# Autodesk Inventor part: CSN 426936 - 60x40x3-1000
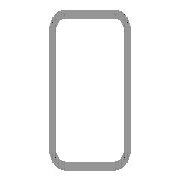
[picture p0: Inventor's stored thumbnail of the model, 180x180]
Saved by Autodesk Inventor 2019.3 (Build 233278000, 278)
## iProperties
Created: 2018-01
Part Number: CSN 426936 - 60x40x3-1000
Material: Ocel, měkká
Description: Tenkostěnné profily ocelové svařované (obdélníkový profil)
Document SubType Name: Modellieren
Standard: CSN 42 6936
Designer: B-hon
Standards Organization: CSN
Language: cs-CZ
Size Designation: 60x40x3-1000
Categories: <MemberInstance><Categories><Category DisplayName="Konstrukční profily" InternalName="089c4875-fa83-4c05-b084-43b9cc11f5ed" Mnemonic="GRDR"><CategoryParameter D
Stock Number: 60x40x3
Density: 7.85 g/cm^3
Appearance: Pololeštěná
IsCustomPart: 1
G_L: 1000,000 mm
Author: B-hon
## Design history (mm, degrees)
node "Počáteční rovina"
node "Koncová rovina"
sketch "Náčrt1"
  geometry: L1 (-14, 30)-(14, 30); L2 (20, 24)-(20, -24); L3 (14, -30)-(-14, -30); L4 (-20, -24)-(-20, 24); L5 (-21.87, 0)-(21.87, 0) reference; L6 (0, -35.87)-(0, 35.87) reference; L7 (-14, 27)-(14, 27); L8 (17, 24)-(17, -24); L9 (14, -27)-(-14, -27); L10 (-17, -24)-(-17, 24); A1 r 6 centre (-14, 24) between (-14, 30) and (-20, 24); A2 r 6 centre (14, 24) between (20, 24) and (14, 30); A3 r 6 centre (14, -24) between (14, -30) and (20, -24); A4 r 6 centre (-14, -24) between (-20, -24) and (-14, -30); A5 r 3 centre (-14, 24) between (-14, 27) and (-17, 24); A6 r 3 centre (14, 24) between (17, 24) and (14, 27); A7 r 3 centre (14, -24) between (14, -27) and (17, -24); A8 r 3 centre (-14, -24) between (-17, -24) and (-14, -27); 3 further points
  constraints: 16 end point, 16 point on circle, 8 centre point, 8 tangent, 6 point on line, 4 parallel, 3 equal radius, 2 perpendicular, 1 horizontal, 7 other
  dimensions: "b" = 40 distance of point (-20, 30) point (20, 30); "ParH" = 60 distance of point (20, 30) point (20, -30); "msp_r" = 6 radius of A1 (= 2 x ParT); "d8" = 20 distance between parallel lines of L4 L6 (= 0.5 x b); "d9" = 30 distance between parallel lines of L5 L1 (= 0.5 x ParH); "d10" = 3 distance between parallel lines of L4 L10 (= ParT)
extrude "Těleso" new body sketch "Náčrt1" taper "d4" = 0 deg; stored distance "NLG" = 10
node "Driven Length"
  sketch "Sketch2"
    geometry: L1 (0, 0)-(10, 0) reference
    constraints: 2 end point, 1 horizontal
  workplane "Work Plane3"
  sketch "Sketch3"
    geometry: L1 (-2, 0)-(12, 0) reference; L2 (-2, 1000)-(12, 1000) reference
    dimensions: "d14" = 1000 distance between parallel lines of L1 L2 (derived)
sketch "Náčrt4"
  geometry: L1 (-125.265, 56.649)-(289.394, 144.788); L2 (289.394, 144.788)-(172.945, -252.605); L3 (172.945, -252.605)-(-125.265, 56.649); L4 (14, 0)-(114.92, 0) reference; L5 (-6, 0)-(-6, 1000) reference; L6 (28, 1000)-(0, 1000) reference; 1 further point
  constraints: 8 end point, 2 horizontal, 2 point on line
  dimensions: "d15" = 12 deg angle of L4 L1; "d16" = 918 distance from line of point (-6, 82) L6
extrude "Vysunutí2" cut sketch "Náčrt4" extent not by distance; stored distance "d17" = 0; taper "d18" = 0 deg
body "Solid1"
other parameters: "ParT" = 3, "G_OFFSET_START" = 0 [user parameter; used in 1 equation term], "G_OFFSET_END" = 0 [user parameter; used in 1 equation term], "d11" = 0 (computed from G_OFFSET_START), "G_L" = 1000 (= d14) [user parameter], "d13" = 90 deg
